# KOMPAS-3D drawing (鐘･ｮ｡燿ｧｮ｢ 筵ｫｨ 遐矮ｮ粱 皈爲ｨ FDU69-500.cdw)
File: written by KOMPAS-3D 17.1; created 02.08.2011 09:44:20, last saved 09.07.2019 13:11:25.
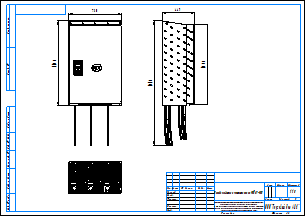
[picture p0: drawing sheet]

Title block, sheet 1: name: Преобразователи частоты серии FDU69-500; scale: 1:10; sheets: 1; sheet format: A3; stored path: \\adlc.lan\data\АДЛ_ПКД\3D-модели\Поставщики\Оборудование Emotron\Преобразователи частоты\Серия FDU 2.0\KOMPAS 2D\Преобразователи частоты серии FDU69-500.cdw

Views: Спереди 1
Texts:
  Рама для чертежей
  Лит-Масса-Масштаб
  Материал-Предприятие
  Масштаб
  Изм.
  Лист
  № докум.
  Подп.
  Дата
  Лит.
  Разраб.
  Пров.
  Т.контр.
  Листов
  Внимание! Данный продукт является объектом авторского права ООО «Торговый Дом АДЛ».
  Запрещается изменение, копирование, распространение
  (в том числе путем копирования на другие сайты и ресурсы в Интернете)
  или любое иное использование информации и объектов без предварительного
  согласия правообладателя (ООО «Торговый Дом АДЛ»).
  Н.контр.
  Утв.
  ООО "Торговый дом АДЛ"
  Изменение
  Номер документа
  Подпись
  Обозначение документа
  Наименование изделия
  Масса изделия по ГОСТ 2.109-73
  Порядковый номер листа
  Общее количество листов в документе
  Характер работы, выполненной лицом, подписавшим документ
  Наименование или индекс предприятия, выпускающего документ
  Инв. № подл.
  Подп. и дата
  Взам. инв. №
  Инв. № дубл.
  Инвентарный номер подлинника по ГОСТ 2.501-68
  Подпись принявшего подлинник в отдел технической документации
  Инвентарный номер подлинника, взамен которого выпущен данный подлинник
  Инвентарный номер дубликата по ГОСТ 2.502-68
  Подпись принявшего дубликат в отдел технической документации
  Справ. №
  Перв. примен.
  Обозначение документа, взамен или на основании которого выпущен данный документ
  Обозначение документа, в котором впервые записан данный документ
  Подпись лица, копировавшего чертеж
  Обозначение формата листа
  !Рама для чертежа
Dimensions and other numbers on the sheet: 1176; 730; 449; 1096; 1718; 1:10; 1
